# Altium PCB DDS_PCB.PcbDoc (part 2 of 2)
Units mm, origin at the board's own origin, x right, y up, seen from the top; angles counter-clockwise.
Board outline 101.55 x 88.3 mm, 8 copper layers (TOP_L1, Plane_L2, Inner_L3, Plane_L4, Plane_L5, Inner_L6, Plane_L7, Bottom Layer_L8), stack 0.681 mm thick; 434 components, 266 nets, 1385 pads, 24 vias.
Unrouted connection lines stored in the file: 977.
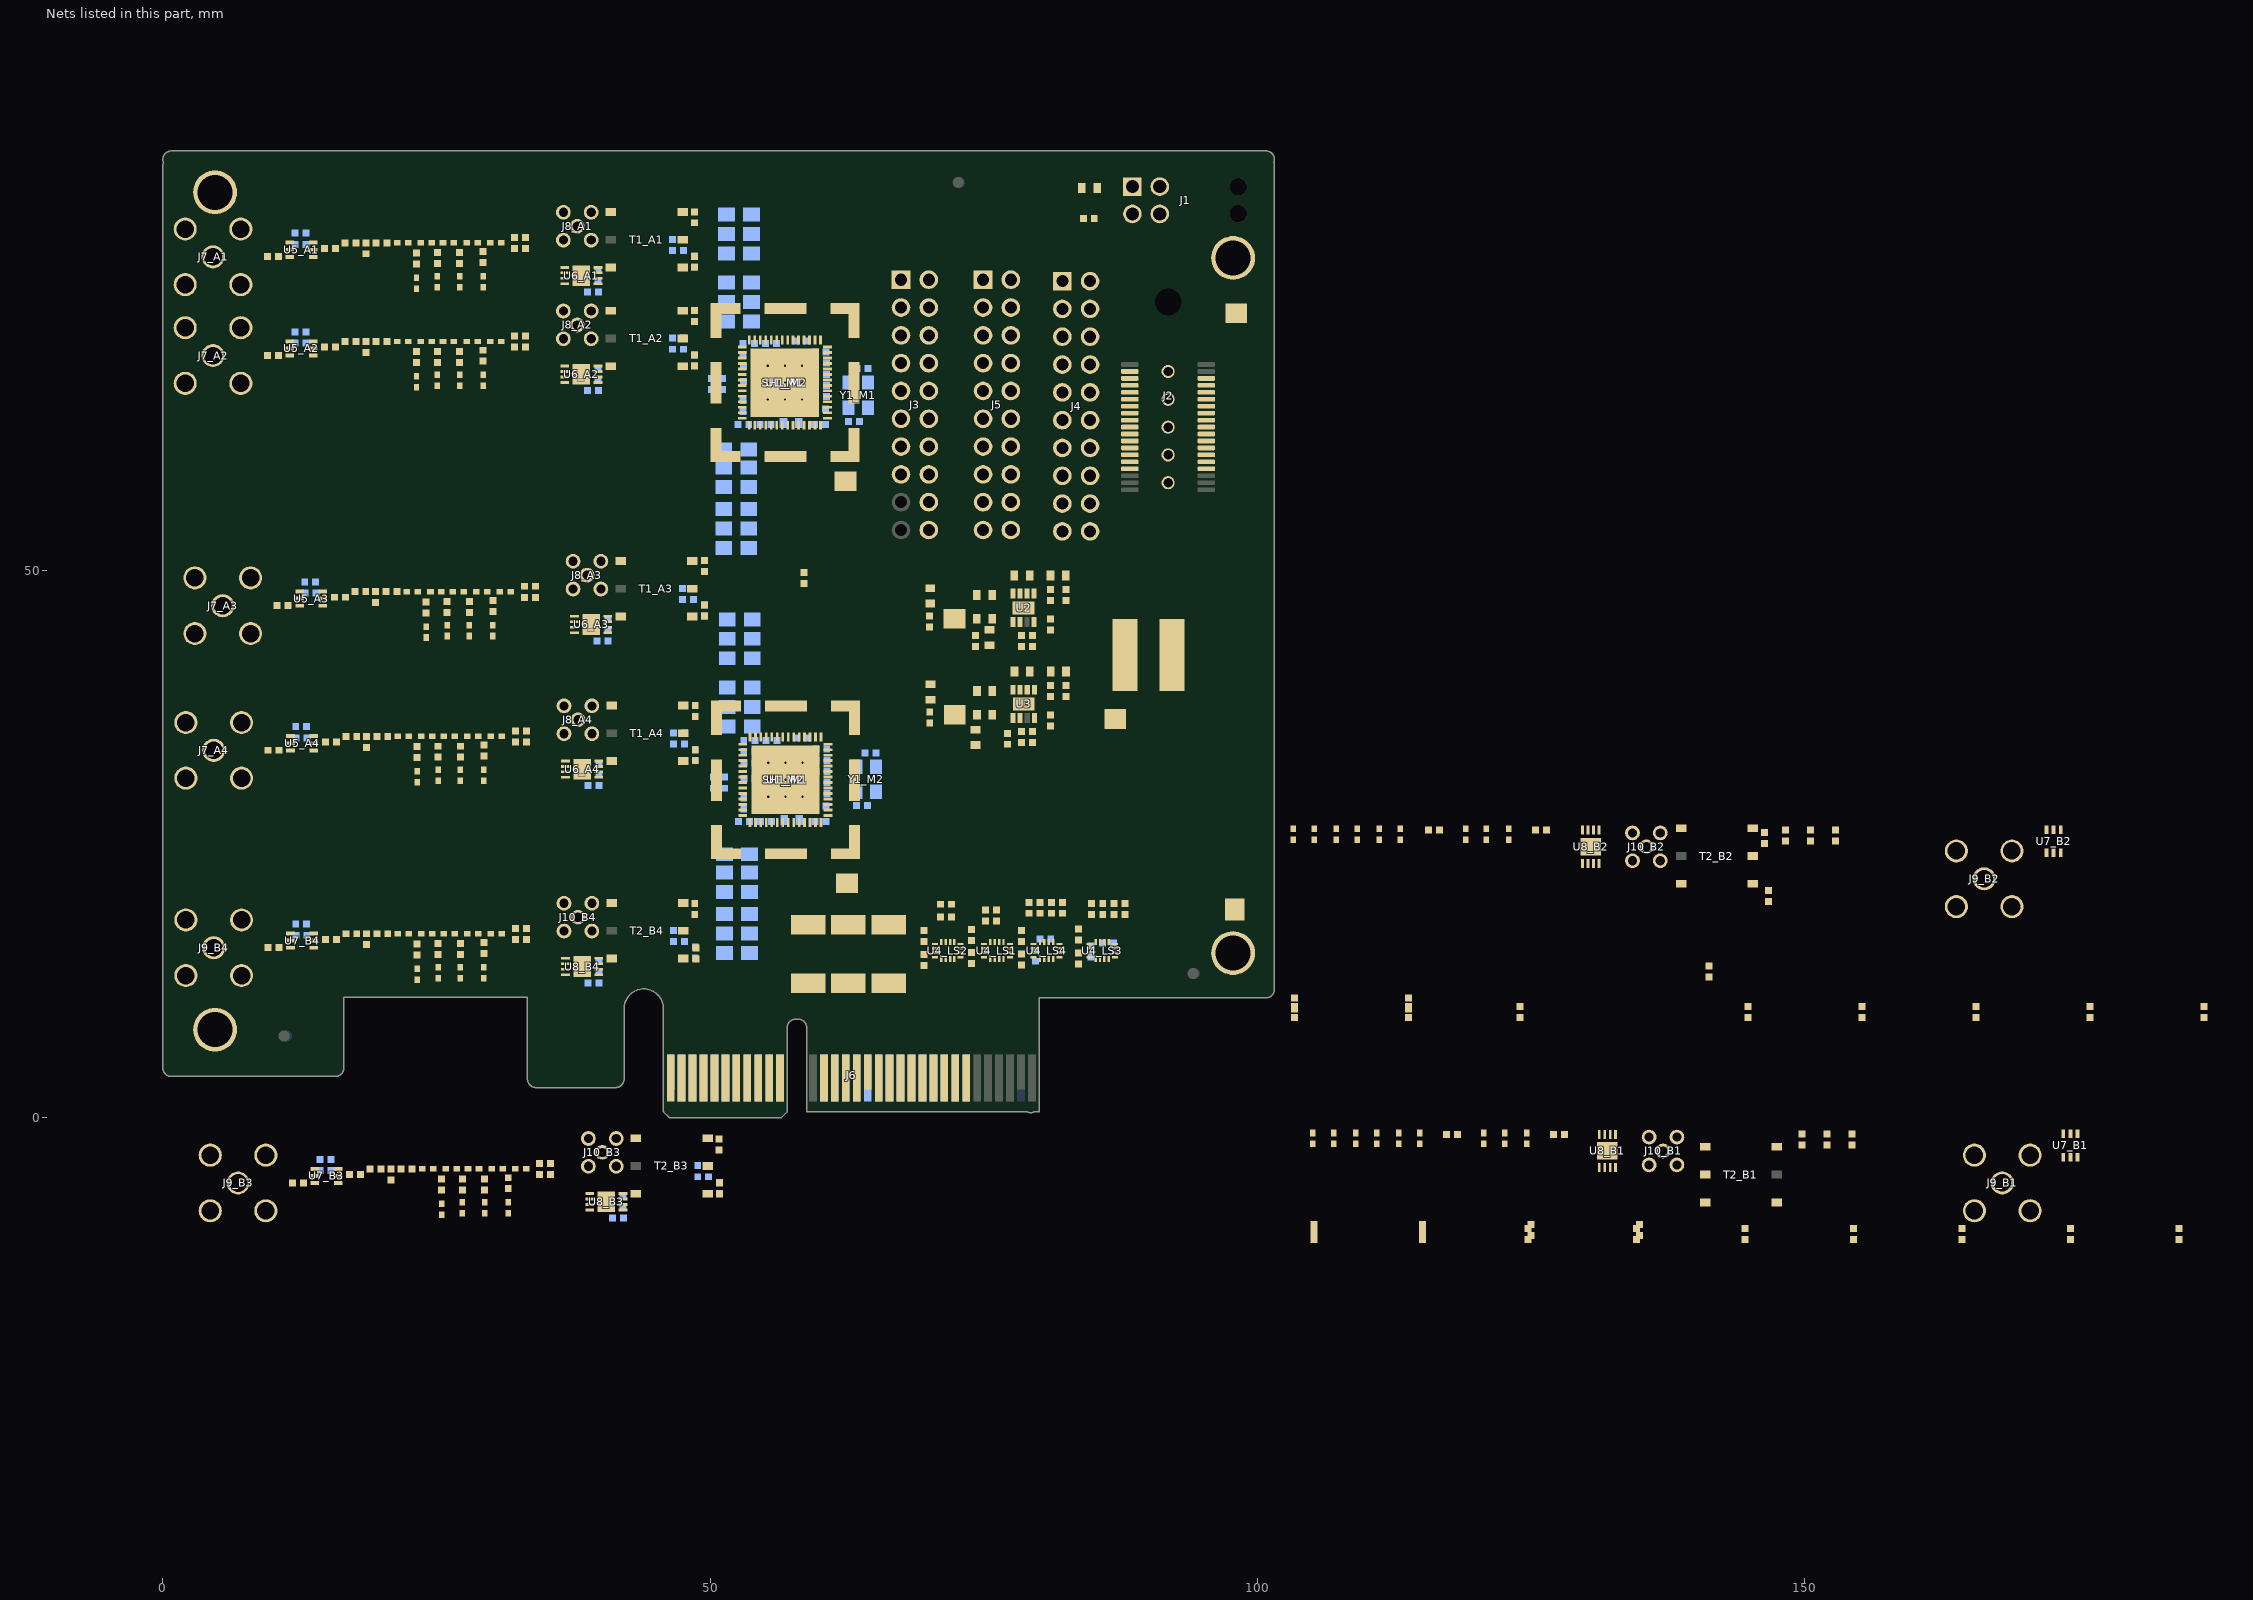
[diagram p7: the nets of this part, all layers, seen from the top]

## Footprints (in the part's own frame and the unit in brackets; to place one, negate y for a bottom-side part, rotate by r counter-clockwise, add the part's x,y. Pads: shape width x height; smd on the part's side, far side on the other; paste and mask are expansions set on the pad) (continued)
SAMTEC_MMCX-J-P-H-ST-TH1 [mm]
  round 1.348 hole 0.84: 1(0,0) S1(-1.27,1.27) S2(1.27,1.27) S3(1.27,-1.27) S4(-1.27,-1.27)
  silkscreen extent -1.75,-1.75 1.75,1.75, body extent -1.75,-1.75 1.75,1.75, height 4.35
SMD4_ECX-32_3P2X2P5_ECS [mm]
  rect 1.1x1.3 smd paste-0.55 mask+0.051: 1(-0.9,1.15) 2(-0.9,-1.15) 3(0.9,-1.15) 4(0.9,1.15)
  silkscreen extent -1.42,-0.17 1.42,0.17, body extent -1.3,-1.65 1.3,1.65, height 0.81
SMS201F [mm]
  rect 1x3.12 smd mask+0.051: 1(-6.3,-5.695) 1(6.3,-5.695)
  rect 1x3.79 smd mask+0.051: 1(-6.3,-0.03) 1(6.3,-0.03)
  rect 1x3.18 smd mask+0.051: 1(-6.3,5.665) 1(6.3,5.665)
  rect 1.75x1 smd mask+0.051: 1(-4.925,-6.755) 1(-4.925,6.755)
  rect 3.81x1 smd mask+0.051: 1(0.045,-6.755) 1(0.045,6.755)
  rect 1.64x1 smd mask+0.051: 1(4.98,-6.755) 1(4.98,6.755)
  silkscreen extent -6.35,-6.84 6.35,6.84, body extent -6.7,-7.15 6.7,7.15, height 2.64
SO8_MUN12AD_DEA [mm]
  rect 0.91x0.458 smd paste+0 mask+0.051: 1(-1.293,0.975) 2(-1.293,0.325) 3(-1.293,-0.325) 4(-1.293,-0.975) 5(1.293,-0.975) 6(1.293,-0.325) 7(1.293,0.325) 8(1.293,0.975)
  rect 1.2x2 smd paste+0 mask+0.051: 9(0,0)
  silkscreen extent -1.57,-1.68 1.57,1.68, body extent -1.45,-1.55 1.45,1.55, height 1.5
SOT_2815,115_NXP [mm]
  rect 0.782x0.355 smd paste+0 mask+0.051: 1(-1.064,0.65) 2(-1.064,0) 3(-1.064,-0.65) 4(1.064,-0.65) 5(1.064,0) 6(1.064,0.65)
  silkscreen extent -0.8,-1.23 0.8,1.23, body extent -1.1,-1.1 1.1,1.1, height 1.09
TP_2X1.8 [mm]
  rect 1.8x2 smd mask+0.051: 1(0,0)
  body extent -0.89,-0.99 0.89,0.99, height 0.03

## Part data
C1_M1 C1_M2: library part "CAP CER 6.8pF 50V NP0 0402", "CAP CER 680PF 50V NP0 0402", Capacitance=680pF, Manufacturer="TDK Corporation", Manufacturer Part Number=C1005C0G1H6R8D, Package / Case="0402 (1005 Metric)", Voltage - Rated=50V
C2_M1 C2_M2 C3_M1 C3_M2: library part "CAP CER 6.8pF 50V NP0 0402", "CAP CER 39PF 50V NP0 0402", Capacitance=39pF, Manufacturer="TDK Corporation", Manufacturer Part Number=C1005C0G1H6R8D, Package / Case="0402 (1005 Metric)", Voltage - Rated=50V
C4_M1 C4_M2 C5_M1 C5_M2 C6_M1 C6_M2 C31_A1 C31_A2 C31_A3 C31_A4 C32_A1 C32_A2 C32_A3 C32_A4 C37_A1 C37_A2 C37_A3 C37_A4 C40_A1 C40_A2 C40_A3 C40_A4 C44_B1 C44_B2 C44_B3 C44_B4 C45_B1 C45_B2 C45_B3 C45_B4 C50_B1 C50_B2 C50_B3 C50_B4 C53_B1 C53_B2 C53_B3 C53_B4: library part "CAP CER 6.8pF 50V NP0 0402", "CAP CER 1uF 25V X5R 0402", Capacitance=1uF, Manufacturer="TDK Corporation", Manufacturer Part Number=C1005C0G1H6R8D, Package / Case="0402 (1005 Metric)", Voltage - Rated=50V
C7_M1 C7_M2 C8_M1 C8_M2 C9_M1 C9_M2 C43_A1 C43_A2 C43_A3 C43_A4 C56_B1 C56_B2 C56_B3 C56_B4: library part "CAP CER 6.8pF 50V NP0 0402", "CAP CER 10uF 10V X5R 0402", Capacitance=10uF, Manufacturer="TDK Corporation", Manufacturer Part Number=C1005C0G1H6R8D, Package / Case="0402 (1005 Metric)", Voltage - Rated=50V
C10_M1 C10_M2 C11_M1 C11_M2 C12_M1 C12_M2 C29_LS1 C29_LS2 C29_LS3 C29_LS4 C30_LS1 C30_LS2 C30_LS3 C30_LS4 C38_A1 C38_A2 C38_A3 C38_A4 C39_A1 C39_A2 C39_A3 C39_A4 C41_A1 C41_A2 C41_A3 C41_A4 C42_A1 C42_A2 C42_A3 C42_A4 C51_B1 C51_B2 C51_B3 C51_B4 C52_B1 C52_B2 C52_B3 C52_B4 C54_B1 C54_B2 C54_B3 C54_B4 C55_B1 C55_B2 C55_B3 C55_B4: library part "CAP CER 6.8pF 50V NP0 0402", "CAP CER 0.1uF 50V NP0 0402", Capacitance=0.1uF, Manufacturer="TDK Corporation", Manufacturer Part Number=C1005C0G1H6R8D, Package / Case="0402 (1005 Metric)", Voltage - Rated=50V
C13 C20 C26: library part "CAP CER 10uF 10V 10% X5R 0603", "CAP CER 10UF 25V 10% X5R 0603", Capacitance=10µF, Manufacturer="TDK Corporation", Manufacturer Part Number=C1608X5R1A106K, Package / Case="0603 (1608 Metric)", Voltage - Rated=10V
C14 C15 C18 C19 C22 C24 C25: library part "CAP CER 12nF 25V 10% X7R 0402", "CAP CER 10nF 25V 10% X5R 0402", Capacitance=10nF, Manufacturer="Murata Electronics North America", Manufacturer Part Number=GRM155R71E123KA61D, Package / Case="0402 (1005 Metric)", Voltage - Rated=25V
C16 C17 C23 C27: library part "CAP CER 10uF 10V 10% X5R 0603", "CAP CER 22UF 16V 10% X5R 0603", Capacitance=22µF, Manufacturer="TDK Corporation", Manufacturer Part Number=C1608X5R1A106K, Package / Case="0603 (1608 Metric)", Voltage - Rated=10V
C21 C28: library part "CAP CER 6.8pF 50V NP0 0402", "CAP CER NA 50V NP0 0402", Manufacturer="TDK Corporation", Manufacturer Part Number=C1005C0G1H6R8D, Package / Case="0402 (1005 Metric)", Voltage - Rated=50V
C33_A1 C33_A2 C33_A3 C33_A4 C46_B1 C46_B2 C46_B3 C46_B4: library part "CAP CER 20pF 50V 5% NP0 0402", "CAP CER 16PF 50V 5% NP0 0402", Capacitance=16pF, Manufacturer="TDK Corporation", Manufacturer Part Number=C1005C0G1H200J, Package / Case="0402 (1005 Metric)", Voltage - Rated=50V
C34_A1 C34_A2 C34_A3 C34_A4 C47_B1 C47_B2 C47_B3 C47_B4: library part "CAP CER 20pF 50V 5% NP0 0402", "CAP CER 11PF 50V 5% NP0 0402", Capacitance=11pF, Manufacturer="TDK Corporation", Manufacturer Part Number=C1005C0G1H200J, Package / Case="0402 (1005 Metric)", Voltage - Rated=50V
C35_A1 C35_A2 C35_A3 C35_A4 C48_B1 C48_B2 C48_B3 C48_B4: library part "CAP CER 20pF 50V 5% NP0 0402", "CAP CER 10PF 50V 5% NP0 0402", Capacitance=10pF, Manufacturer="TDK Corporation", Manufacturer Part Number=C1005C0G1H200J, Package / Case="0402 (1005 Metric)", Voltage - Rated=50V
C36_A1 C36_A2 C36_A3 C36_A4 C49_B1 C49_B2 C49_B3 C49_B4: library part "CAP CER 20pF 50V 5% NP0 0402", "CAP CER 13PF 50V 5% NP0 0402", Capacitance=13pF, Manufacturer="TDK Corporation", Manufacturer Part Number=C1005C0G1H200J, Package / Case="0402 (1005 Metric)", Voltage - Rated=50V
F1 F2 F3: library part 1812L150/24MR, "FUSE PTC 24V 1.5A POLYFUSE 1812", Current - Hold (Ih) (Max)=1.5A, Manufacturer="Littelfuse Inc", Package / Case="1812 (4532 Metric), Concave"
FB1_M1 FB1_M2 FB2 FB3 FB4 FB5: library part BK1608HS600-T, "FERRITE BEAD 220_OHM@100MHz 0603 2A 50mohm_DC", Manufacturer="Taiyo Yuden", Package / Case="0603 (1608 Metric)"
H1 H2 H3 H4: "hole 3mm"
J1: "No Description Available", Mfr_Name="Molex Connector Corporation"
J2: "CONN MICTOR 38POS .025 VERT SMD", Manufacturer="TE Connectivity"
J3 J4 J5: "CONN HEADER 20 TH", Manufacturer="Molex Connector Corporation"
J6: "64 Position Female Connector PCI Expressâ„¢ Gold 0.039 _1.00mm_ Black", Package=None
J7_A1 J7_A2 J7_A3 J7_A4 J9_B1 J9_B2 J9_B3 J9_B4: "No Description Available", Mfr_Name="Samtec Inc"
J8_A1 J8_A2 J8_A3 J8_A4 J10_B1 J10_B2 J10_B3 J10_B4: "MMCX STRAIGHT, THROUGH HOLE JACK- 50 OHM", Package=None
LD1 LD2: "LED 1.6X0.8MM 568NM GRN CLR SMD", Manufacturer="Kingbright Corp", Package / Case="0603 (1608 Metric)"
Lp1: "INDUCTOR 10UH 1.9A 20% SMD", Manufacturer="Taiyo Yuden", Package / Case="Non Standard"
R1_M1 R1_M2: library part "RES 3.09K OHM 1/16W 1% 0402", "RES 6.8K OHM 1/16W 1% 0402", Manufacturer="Stackpole Electronics Inc", Manufacturer Part Number=RMCF0402FT3K09, Package / Case="0402 (1005 Metric)", Power (Watts)="0.063W, 1/16W", Supplier Device Package=0402
R2_M1 R2_M2 R7_M1 R7_M2 R8_M1 R8_M2 R9_M1 R9_M2 R10_M1 R10_M2 R33 R41_A1 R41_A2 R41_A3 R41_A4 R42_A1 R42_A2 R42_A3 R42_A4 R48_B1 R48_B2 R48_B3 R48_B4 R49_B1 R49_B2 R49_B3 R49_B4: library part "RES 100 OHM 1/10W 1% 0402 SMD", "RES 0 OHM 1/10W 1% 0402 SMD", Manufacturer="Panasonic Electronic Components", Manufacturer Part Number=ERJ-2RKF1000X, Package / Case="0402 (1005 Metric)", Supplier Device Package=0402
R3_M1 R3_M2 R4_M1 R4_M2 R5_M1 R5_M2 R6_M1 R6_M2 R11_M1 R11_M2 R12_M1 R12_M2 R13_M1 R13_M2 R14_M1 R14_M2: library part "RES 3.09K OHM 1/16W 1% 0402", "RES 10K OHM 1/16W 1% 0402", Manufacturer="Stackpole Electronics Inc", Manufacturer Part Number=RMCF0402FT3K09, Package / Case="0402 (1005 Metric)", Power (Watts)="0.063W, 1/16W", Supplier Device Package=0402
R15_M1 R15_M2 R16_M1 R16_M2 R17_M1 R17_M2 R18_M1 R18_M2 R19_M1 R19_M2 R20_M1 R20_M2 R21_M1 R21_M2 R22_M1 R22_M2 R23_M1 R23_M2 R24_M1 R24_M2 R25_M1 R25_M2 R26_M1 R26_M2: library part "RES 200 OHM 1/8W 1% 0805 SMD", "RES 0 OHM 1/8W 1% 0805 SMD", Manufacturer="Stackpole Electronics Inc", Manufacturer Part Number=RMCF0805FT200R, Package / Case="0805 (2012 Metric)", Power (Watts)="0.125W, 1/8W", Supplier Device Package=0805
R27 R30: library part "RES 15.4K OHM 1/10W 1% 0402 SMD", "RES 124K OHM 1/10W 1% 0402 SMD", Manufacturer="Panasonic Electronic Components", Manufacturer Part Number=ERJ-2RKF1542X, Package / Case="0402 (1005 Metric)", Power (Watts)="0.1W, 1/10W", Supplier Device Package=0402
R28 R31: library part "RES 3.09K OHM 1/16W 1% 0402", "RES 1K OHM 1/16W 1% 0402", Manufacturer="Stackpole Electronics Inc", Manufacturer Part Number=RMCF0402FT3K09, Package / Case="0402 (1005 Metric)", Power (Watts)="0.063W, 1/16W", Supplier Device Package=0402
R29: library part "RES 15.4K OHM 1/10W 1% 0402 SMD", "RES 39.2K OHM 1/10W 1% 0402 SMD", Manufacturer="Panasonic Electronic Components", Manufacturer Part Number=ERJ-2RKF1542X, Package / Case="0402 (1005 Metric)", Power (Watts)="0.1W, 1/10W", Supplier Device Package=0402
R32 R34_LS1 R34_LS2 R34_LS3 R34_LS4: library part "RES 3.09K OHM 1/16W 1% 0402", "RES 100K OHM 1/16W 1% 0402", Manufacturer="Stackpole Electronics Inc", Manufacturer Part Number=RMCF0402FT3K09, Package / Case="0402 (1005 Metric)", Power (Watts)="0.063W, 1/16W", Supplier Device Package=0402
R35_LS1 R35_LS2 R35_LS3 R35_LS4: library part "RES 3.09K OHM 1/16W 1% 0402", "RES 3.09K OHM 1/16W 1% 0402", Manufacturer="Stackpole Electronics Inc", Manufacturer Part Number=RMCF0402FT3K09, Package / Case="0402 (1005 Metric)", Power (Watts)="0.063W, 1/16W", Supplier Device Package=0402
R36_A1 R36_A2 R36_A3 R36_A4 R37_A1 R37_A2 R37_A3 R37_A4 R43_B1 R43_B2 R43_B3 R43_B4 R44_B1 R44_B2 R44_B3 R44_B4: library part "RES 100 OHM 1/10W 1% 0402 SMD", "RES 34.8 OHM 1/10W 1% 0402 SMD", Manufacturer="Panasonic Electronic Components", Manufacturer Part Number=ERJ-2RKF1000X, Package / Case="0402 (1005 Metric)", Supplier Device Package=0402
R38_A1 R38_A2 R38_A3 R38_A4 R45_B1 R45_B2 R45_B3 R45_B4: library part "RES 100 OHM 1/10W 1% 0402 SMD", "RES 18.2 OHM 1/10W 1% 0402 SMD", Manufacturer="Panasonic Electronic Components", Manufacturer Part Number=ERJ-2RKF1000X, Package / Case="0402 (1005 Metric)", Supplier Device Package=0402
R39_A1 R39_A2 R39_A3 R39_A4 R40_A1 R40_A2 R40_A3 R40_A4 R46_B1 R46_B2 R46_B3 R46_B4 R47_B1 R47_B2 R47_B3 R47_B4: library part "RES 100 OHM 1/10W 1% 0402 SMD", "RES 49.9 OHM 1/10W 1% 0402 SMD", Manufacturer="Panasonic Electronic Components", Manufacturer Part Number=ERJ-2RKF1000X, Package / Case="0402 (1005 Metric)", Supplier Device Package=0402
SH1_M1 SH1_M2: "RF SHIELD 0.5\" X 0.538\" SMD", Manufacturer="Leader Tech Inc.", Manufacturer_Part_Number=SMS-201F
T1_A1 T1_A2 T1_A3 T1_A4 T2_B1 T2_B2 T2_B3 T2_B4: "No Description Available", Mfr_Name="Mini Circuits"
TP1 TP2 TP3 TP4 TP5 TP6: library part "TP mini_2", "TP PC MINIATURE SMT", Manufacturer="Keystone Electronics", Manufacturer Part Number=5015
TP7: library part "TP mini_1", "TP PC MINIATURE SMT", Manufacturer="Keystone Electronics", Manufacturer Part Number=5015
U1_M1 U1_M2 U6_A1 U6_A2 U6_A3 U6_A4 U8_B1 U8_B2 U8_B3 U8_B4: "No Description Available", Mfr_Name="Analog Devices Inc"
U2 U3: "No Description Available", Mfr_Name=Delta
U5_A1 U5_A2 U5_A3 U5_A4 U7_B1 U7_B2 U7_B3 U7_B4: "No Description Available", Mfr_Name=NXP
Y1_M1 Y1_M2: "No Description Available", Mfr_Name="ECS International"

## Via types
v1: diameter 0.406, hole 0.203, TOP_L1 to Bottom Layer_L8, tented both sides, 18 vias
v2: diameter 0.65, hole 0.3, TOP_L1 to Bottom Layer_L8, tented both sides, 6 vias

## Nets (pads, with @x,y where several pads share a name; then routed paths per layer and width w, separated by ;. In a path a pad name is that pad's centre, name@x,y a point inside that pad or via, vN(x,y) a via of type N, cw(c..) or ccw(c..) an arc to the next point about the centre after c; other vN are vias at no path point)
1.8V: C23.2 C27.2 FB5.1 R30.2 U3.4 U3.5
1_8V: F2.1 J6.B5 J6.B6 J6.B7 J6.B8
3.3V: C16.2 C17.2 FB3.1 R27.2 U2.4 U2.5
3_3V: F1.1 J6.B1 J6.B2 J6.B3 J6.B4
12_V: F3.2 J6.A1 J6.A2 J6.A3 J6.A4
12v_1: C19.2 C20.2 FB2.2 U2.1 U2.2
12v_2: C25.2 C26.2 FB4.2 U3.1 U3.2
12v_in: C13.2 C14.2 J1.1 J1.2 Lp1.1
AVDD0_M1: C41_A1.2 C42_A1.2 C43_A1.2 C54_B1.2 C55_B1.2 C56_B1.2 R18_M1.2 R22_M1.2 R26_M1.2 R39_A1.2 R40_A1.1 R46_B1.2 R47_B1.1 T1_A1.2 T2_B1.2
AVDD0_M2: C41_A3.2 C42_A3.2 C43_A3.2 C54_B3.2 C55_B3.2 C56_B3.2 R18_M2.2 R22_M2.2 R26_M2.2 R39_A3.2 R40_A3.1 R46_B3.2 R47_B3.1 T1_A3.2 T2_B3.2
AVDD1_M1: C41_A2.2 C42_A2.2 C43_A2.2 C54_B2.2 C55_B2.2 C56_B2.2 R17_M1.2 R18_M1.1 R21_M1.2 R22_M1.1 R25_M1.2 R26_M1.1 R39_A2.2 R40_A2.1 R46_B2.2 R47_B2.1 T1_A2.2 T2_B2.2
AVDD1_M2: C41_A4.2 C42_A4.2 C43_A4.2 C54_B4.2 C55_B4.2 C56_B4.2 R17_M2.2 R18_M2.1 R21_M2.2 R22_M2.1 R25_M2.2 R26_M2.1 R39_A4.2 R40_A4.1 R46_B4.2 R47_B4.1 T1_A4.2 T2_B4.2
AVDD2_M1: R16_M1.2 R17_M1.1 R20_M1.2 R21_M1.1 R24_M1.2 R25_M1.1
AVDD2_M2: R16_M2.2 R17_M2.1 R20_M2.2 R21_M2.1 R24_M2.2 R25_M2.1
AVDD3_M1: R15_M1.2 R16_M1.1 R19_M1.2 R20_M1.1 R23_M1.2 R24_M1.1
AVDD3_M2: R15_M2.2 R16_M2.1 R19_M2.2 R20_M2.1 R23_M2.2 R24_M2.1
CH_B1_N: R47_B1.2 T2_B1.1
CH_B1_P: R46_B1.1 T2_B1.3
CH_B2_N: R47_B2.2 T2_B2.1
CH_B2_P: R46_B2.1 T2_B2.3
CH_B3_N: R47_B3.2 T2_B3.1
CH_B3_P: R46_B3.1 T2_B3.3
CH_B4_N: R47_B4.2 T2_B4.1
CH_B4_P: R46_B4.1 T2_B4.3
CH_N0_M1: R40_A1.2 T1_A1.3 U1_M1.29
CH_N0_M2: R40_A3.2 T1_A3.3 U1_M2.29
CH_N1_M1: R40_A2.2 T1_A2.3 U1_M1.35
CH_N1_M2: R40_A4.2 T1_A4.3 U1_M2.35
CH_N2_M1: U1_M1.9
CH_N2_M2: U1_M2.9
CH_N3_M1: U1_M1.14
CH_N3_M2: U1_M2.14
CH_P0_M1: R39_A1.1 T1_A1.1 U1_M1.30
CH_P0_M2: R39_A3.1 T1_A3.1 U1_M2.30
CH_P1_M1: R39_A2.1 T1_A2.1 U1_M1.36
CH_P1_M2: R39_A4.1 T1_A4.1 U1_M2.36
CH_P2_M1: U1_M1.8
CH_P2_M2: U1_M2.8
CH_P3_M1: U1_M1.13
CH_P3_M2: U1_M2.13
CLK_sel_M1: R8_M1.1 R10_M1.2 U1_M1.24
CLK_sel_M2: R8_M2.1 R10_M2.2 U1_M2.24
contr0_M1: J2.26 J3.1 J6.B13 U6_A1.2 U8_B1.2
contr0_M2: J2.25 J3.9 J6.A13 U6_A3.2 U8_B3.2
contr1_M1: J2.28 J3.3 J6.B14 U6_A2.2 U8_B2.2
contr1_M2: J2.27 J3.11 J6.A14 U6_A4.2 U8_B4.2
contr2_M1: J2.30 J3.5 J6.B15
contr2_M2: J2.29 J3.13 J6.A15
contr3_M1: J2.32 J3.7 J6.B16
contr3_M2: J2.31 J3.15 J6.A16
CSn: U1_M1.47 U4_LS2.12
CSn_2: U1_M2.47 U4_LS1.12
CSn_2_L: J2.7 J5.3 J6.A18 U4_LS1.1
CSn_L: J2.8 J4.3 J6.B18 U4_LS2.1
DAC_O_A1: T1_A1.6 U6_A1.4
DAC_O_A2: T1_A2.6 U6_A2.4
DAC_O_A3: T1_A3.6 U6_A3.4
DAC_O_A4: T1_A4.6 U6_A4.4
DAC_O_B1: T2_B1.4 U8_B1.4
DAC_O_B2: T2_B2.4 U8_B2.4
DAC_O_B3: T2_B3.4 U8_B3.4
DAC_O_B4: T2_B4.4 U8_B4.4
DIR_LS1: J2.21 J5.17 J6.A25 R34_LS1.1 R34_LS4.1 R35_LS1.2 R35_LS4.2 U4_LS1.5 U4_LS1.6 U4_LS1.15 U4_LS1.16 U4_LS4.5 U4_LS4.6 U4_LS4.15 U4_LS4.16
DIR_LS2: J2.22 J4.17 J6.B25 R34_LS2.1 R34_LS3.1 R35_LS2.2 R35_LS3.2 U4_LS2.5 U4_LS2.6 U4_LS2.15 U4_LS2.16 U4_LS3.5 U4_LS3.6 U4_LS3.15 U4_LS3.16
FB_1.8: R30.1 R32.2 U3.6
FB_3.3: R27.1 R29.2 U2.6
GND: C2_M1.2 C2_M2.2 C3_M1.1 C3_M2.1 C4_M1.1 C4_M2.1 C5_M1.1 C5_M2.1 C6_M1.1 C6_M2.1 C7_M1.1 C7_M2.1 C8_M1.1 C8_M2.1 C9_M1.1 C9_M2.1 C10_M1.1 C10_M2.1 C11_M1.1 C11_M2.1 C12_M1.1 C12_M2.1 C13.1 C14.1 C15.1 C16.1 C17.1 C18.1 C19.1 C20.1 C21.1 C22.1 C23.1 C24.1 C25.1 C26.1 C27.1 C28.1 C29_LS1.1 C29_LS2.1 C29_LS3.1 C29_LS4.1 C30_LS1.1 C30_LS2.1 C30_LS3.1 C30_LS4.1 C37_A1.1 C37_A2.1 C37_A3.1 C37_A4.1 C38_A1.1 C38_A2.1 C38_A3.1 C38_A4.1 C39_A1.1 C39_A2.1 C39_A3.1 C39_A4.1 C40_A1.1 C40_A2.1 C40_A3.1 C40_A4.1 C41_A1.1 C41_A2.1 C41_A3.1 C41_A4.1 C42_A1.1 C42_A2.1 C42_A3.1 C42_A4.1 C43_A1.1 C43_A2.1 C43_A3.1 C43_A4.1 C50_B1.1 C50_B2.1 C50_B3.1 C50_B4.1 C51_B1.1 C51_B2.1 C51_B3.1 C51_B4.1 C52_B1.1 C52_B2.1 C52_B3.1 C52_B4.1 C53_B1.1 C53_B2.1 C53_B3.1 C53_B4.1 C54_B1.1 C54_B2.1 C54_B3.1 C54_B4.1 C55_B1.1 C55_B2.1 C55_B3.1 C55_B4.1 C56_B1.1 C56_B2.1 C56_B3.1 C56_B4.1 H1.1 H2.1 H3.1 H4.1 J1.3 J1.4 J2.3 J2.39 J2.40 J2.41 J2.42 J2.43 J3.2 J3.4 J3.6 J3.8 J3.10 J3.12 J3.14 J3.16 J3.18 J3.20 J4.2 J4.4 J4.6 J4.8 J4.10 J4.12 J4.14 J4.16 J4.18 J4.20 J5.2 J5.4 J5.6 J5.8 J5.10 J5.12 J5.14 J5.16 J5.18 J5.20 J6.A5 J6.A6 J6.A7 J6.A8 J6.A9 J6.A10 J6.A11 J6.B9 J6.B10 J6.B11 J7_A1.2 J7_A1.3 J7_A1.4 J7_A1.5 J7_A2.2 J7_A2.3 J7_A2.4 J7_A2.5 J7_A3.2 J7_A3.3 J7_A3.4 J7_A3.5 J7_A4.2 J7_A4.3 J7_A4.4 J7_A4.5 J8_A1.S1 J8_A1.S2 J8_A1.S3 J8_A1.S4 J8_A2.S1 J8_A2.S2 J8_A2.S3 J8_A2.S4 J8_A3.S1 J8_A3.S2 J8_A3.S3 J8_A3.S4 J8_A4.S1 J8_A4.S2 J8_A4.S3 J8_A4.S4 J9_B1.2 J9_B1.3 J9_B1.4 J9_B1.5 J9_B2.2 J9_B2.3 J9_B2.4 J9_B2.5 J9_B3.2 J9_B3.3 J9_B3.4 J9_B3.5 J9_B4.2 J9_B4.3 J9_B4.4 J9_B4.5 J10_B1.S1 J10_B1.S2 J10_B1.S3 J10_B1.S4 J10_B2.S1 J10_B2.S2 J10_B2.S3 J10_B2.S4 J10_B3.S1 J10_B3.S2 J10_B3.S3 J10_B3.S4 J10_B4.S1 J10_B4.S2 J10_B4.S3 J10_B4.S4 L6_A1.2 L6_A2.2 L6_A3.2 L6_A4.2 L7_A1.2 L7_A2.2 L7_A3.2 L7_A4.2 L8_A1.2 L8_A2.2 L8_A3.2 L8_A4.2 L9_A1.2 L9_A2.2 L9_A3.2 L9_A4.2 L15_B1.2 L15_B2.2 L15_B3.2 L15_B4.2 L16_B1.2 L16_B2.2 L16_B3.2 L16_B4.2 L17_B1.2 L17_B2.2 L17_B3.2 L17_B4.2 L18_B1.2 L18_B2.2 L18_B3.2 L18_B4.2 LD1.2 LD2.2 R1_M1.1 R1_M2.1 R3_M1.1 R3_M2.1 R4_M1.1 R4_M2.1 R5_M1.1 R5_M2.1 R6_M1.1 R6_M2.1 R9_M1.1 R9_M2.1 R10_M1.1 R10_M2.1 R11_M1.1 R11_M2.1 R12_M1.1 R12_M2.1 R13_M1.1 R13_M2.1 R14_M1.1 R14_M2.1 R29.1 R32.1 R35_LS1.1 R35_LS2.1 R35_LS3.1 R35_LS4.1 R38_A1.2 R38_A2.2 R38_A3.2 R38_A4.2 R45_B1.2 R45_B2.2 R45_B3.2 R45_B4.2 SH1_M1.1 SH1_M2.1 T1_A1.4 T1_A2.4 T1_A3.4 T1_A4.4 T2_B1.6 T2_B2.6 T2_B3.6 T2_B4.6 TP6.1 TP7.1 U1_M1.6 U1_M1.10 U1_M1.12 U1_M1.16 U1_M1.18 U1_M1.20 U1_M1.25 U1_M1.28 U1_M1.32 U1_M1.34 U1_M1.38 U1_M1.44 U1_M1.56 U1_M1.57 U1_M2.6 U1_M2.10 U1_M2.12 U1_M2.16 U1_M2.18 U1_M2.20 U1_M2.25 U1_M2.28 U1_M2.32 U1_M2.34 U1_M2.38 U1_M2.44 U1_M2.56 U1_M2.57 U2.3 U2.9 U3.3 U3.9 U4_LS1.7 U4_LS1.8 U4_LS2.7 U4_LS2.8 U4_LS3.7 U4_LS3.8 U4_LS4.7 U4_LS4.8 U5_A1.2 U5_A1.4 U5_A1.5 U5_A2.2 U5_A2.4 U5_A2.5 U5_A3.2 U5_A3.4 U5_A3.5 U5_A4.2 U5_A4.4 U5_A4.5 U6_A1.3 U6_A1.5 U6_A1.6 U6_A1.7 U6_A1.9 U6_A2.3 U6_A2.5 U6_A2.6 U6_A2.7 U6_A2.9 U6_A3.3 U6_A3.5 U6_A3.6 U6_A3.7 U6_A3.9 U6_A4.3 U6_A4.5 U6_A4.6 U6_A4.7 U6_A4.9 U7_B1.2 U7_B1.4 U7_B1.5 U7_B2.2 U7_B2.4 U7_B2.5 U7_B3.2 U7_B3.4 U7_B3.5 U7_B4.2 U7_B4.4 U7_B4.5 U8_B1.3 U8_B1.5 U8_B1.6 U8_B1.7 U8_B1.9 U8_B2.3 U8_B2.5 U8_B2.6 U8_B2.7 U8_B2.9 U8_B3.3 U8_B3.5 U8_B3.6 U8_B3.7 U8_B3.9 U8_B4.3 U8_B4.5 U8_B4.6 U8_B4.7 U8_B4.9 Y1_M1.2 Y1_M1.4 Y1_M2.2 Y1_M2.4
  other v1: 55.293,29.289 56.868,29.289 58.417,29.289 55.293,30.838 56.868,30.838 58.417,30.838 55.293,32.388 56.868,32.388 58.417,32.388 55.241,65.571 56.816,65.571 58.365,65.571 55.241,67.12 56.816,67.12 58.365,67.12 55.241,68.669 56.816,68.669 58.365,68.669
IO_UPDATE: U1_M1.46 U4_LS2.10
IO_UPDATE_2: U1_M2.46 U4_LS1.10
IO_UPDATE_2_L: J2.9 J5.1 J6.A19 U4_LS1.3
IO_UPDATE_L: J2.10 J4.1 J6.B19 U4_LS2.3
MASTER_RESET: U1_M1.3 U4_LS2.9
MASTER_RESET_2: U1_M2.3 U4_LS1.9
MASTER_RESET_2_L: J2.11 J5.7 J6.A20 U4_LS1.4
MASTER_RESET_L: J2.12 J4.7 J6.B20 U4_LS2.4
NetC1_M1_2: C1_M1.2 R2_M1.2
NetC1_M2_2: C1_M2.2 R2_M2.2
NetC21_2: C21.2 U2.8
NetC28_2: C28.2 U3.8
NetC44_B1_1: C44_B1.1 J9_B1.1
NetC44_B2_1: C44_B2.1 J9_B2.1
NetC44_B3_1: C44_B3.1 J9_B3.1
NetC44_B4_1: C44_B4.1 J9_B4.1
NetC46_B1_1: C46_B1.1 L10_B1.1 L11_B1.2
NetC46_B1_2: C46_B1.2 L15_B1.1
NetC46_B2_1: C46_B2.1 L10_B2.1 L11_B2.2
NetC46_B2_2: C46_B2.2 L15_B2.1
NetC46_B3_1: C46_B3.1 L10_B3.1 L11_B3.2
NetC46_B3_2: C46_B3.2 L15_B3.1
NetC46_B4_1: C46_B4.1 L10_B4.1 L11_B4.2
NetC46_B4_2: C46_B4.2 L15_B4.1
NetC47_B1_1: C47_B1.1 L10_B1.2 L12_B1.1
NetC47_B1_2: C47_B1.2 L16_B1.1
NetC47_B2_1: C47_B2.1 L10_B2.2 L12_B2.1
NetC47_B2_2: C47_B2.2 L16_B2.1
NetC47_B3_1: C47_B3.1 L10_B3.2 L12_B3.1
NetC47_B3_2: C47_B3.2 L16_B3.1
NetC47_B4_1: C47_B4.1 L10_B4.2 L12_B4.1
NetC47_B4_2: C47_B4.2 L16_B4.1
NetC48_B1_1: C48_B1.1 L12_B1.2 L13_B1.1
NetC48_B1_2: C48_B1.2 L17_B1.1
NetC48_B2_1: C48_B2.1 L12_B2.2 L13_B2.1
NetC48_B2_2: C48_B2.2 L17_B2.1
NetC48_B3_1: C48_B3.1 L12_B3.2 L13_B3.1
NetC48_B3_2: C48_B3.2 L17_B3.1
NetC48_B4_1: C48_B4.1 L12_B4.2 L13_B4.1
NetC48_B4_2: C48_B4.2 L17_B4.1
NetC49_B1_1: C49_B1.1 L13_B1.2 L14_B1.1
NetC49_B1_2: C49_B1.2 L18_B1.1
NetC49_B2_1: C49_B2.1 L13_B2.2 L14_B2.1
NetC49_B2_2: C49_B2.2 L18_B2.1
NetC49_B3_1: C49_B3.1 L13_B3.2 L14_B3.1
NetC49_B3_2: C49_B3.2 L18_B3.1
NetC49_B4_1: C49_B4.1 L13_B4.2 L14_B4.1
NetC49_B4_2: C49_B4.2 L18_B4.1
NetJ8_A1_1: J8_A1.1 R41_A1.1
NetJ8_A2_1: J8_A2.1 R41_A2.1
NetJ8_A3_1: J8_A3.1 R41_A3.1
NetJ8_A4_1: J8_A4.1 R41_A4.1
NetJ10_B1_1: J10_B1.1 R48_B1.1
NetJ10_B2_1: J10_B2.1 R48_B2.1
NetJ10_B3_1: J10_B3.1 R48_B3.1
NetJ10_B4_1: J10_B4.1 R48_B4.1
NetL11_B1_1: L11_B1.1 R49_B1.2
NetL11_B2_1: L11_B2.1 R49_B2.2
NetL11_B3_1: L11_B3.1 R49_B3.2
NetL11_B4_1: L11_B4.1 R49_B4.2
NetLD1_1: LD1.1 R28.1
NetLD2_1: LD2.1 R31.1
NetR1_M1_2: R1_M1.2 U1_M1.17
NetR1_M2_2: R1_M2.2 U1_M2.17
NetR2_M1_1: R2_M1.1 U1_M1.27
NetR2_M2_1: R2_M2.1 U1_M2.27
NetR43_B1_1: R43_B1.1 R44_B1.2 R45_B1.1
NetR43_B2_1: R43_B2.1 R44_B2.2 R45_B2.1
NetR43_B3_1: R43_B3.1 R44_B3.2 R45_B3.1
NetR43_B4_1: R43_B4.1 R44_B4.2 R45_B4.1
OUT_A1: L5_A1.2 R37_A1.1
OUT_A2: L5_A2.2 R37_A2.1
OUT_A3: L5_A3.2 R37_A3.1
OUT_A4: L5_A4.2 R37_A4.1
OUT_B1: L14_B1.2 R44_B1.1
OUT_B2: L14_B2.2 R44_B2.1
OUT_B3: L14_B3.2 R44_B3.1
OUT_B4: L14_B4.2 R44_B4.1
P0_M1: R11_M1.2 U1_M1.40
P0_M2: R11_M2.2 U1_M2.40
P1.8V_ana_M1: C1_M1.1 C6_M1.2 C9_M1.2 C12_M1.2 FB1_M1.2 R8_M1.2 R15_M1.1 R19_M1.1 R23_M1.1 U1_M1.5 U1_M1.7 U1_M1.11 U1_M1.15 U1_M1.19 U1_M1.21 U1_M1.26 U1_M1.31 U1_M1.33 U1_M1.37 U1_M1.39
P1.8V_ana_M2: C1_M2.1 C6_M2.2 C9_M2.2 C12_M2.2 FB1_M2.2 R8_M2.2 R15_M2.1 R19_M2.1 R23_M2.1 U1_M2.5 U1_M2.7 U1_M2.11 U1_M2.15 U1_M2.19 U1_M2.21 U1_M2.26 U1_M2.31 U1_M2.33 U1_M2.37 U1_M2.39
P1_M1: R12_M1.2 U1_M1.41
P1_M2: R12_M2.2 U1_M2.41
P2_M1: R13_M1.2 U1_M1.42
P2_M2: R13_M2.2 U1_M2.42
P3_M1: R14_M1.2 U1_M1.43
P3_M2: R14_M2.2 U1_M2.43
P12V: C15.2 C22.2 F3.1 FB2.1 FB4.1 Lp1.2 TP1.1
PWR_DWN_CTR_M1: R7_M1.1 R9_M1.2 U1_M1.4
PWR_DWN_CTR_M2: R7_M2.1 R9_M2.2 U1_M2.4
REF_CLK_M1_N: C3_M1.2 U1_M1.22 Y1_M1.1
REF_CLK_M1_P: C2_M1.1 U1_M1.23 Y1_M1.3
REF_CLK_M2_N: C3_M2.2 U1_M2.22 Y1_M2.1
REF_CLK_M2_P: C2_M2.1 U1_M2.23 Y1_M2.3
RF_1_A1: L2_A1.1 R42_A1.2
RF_1_A2: L2_A2.1 R42_A2.2
RF_1_A3: L2_A3.1 R42_A3.2
RF_1_A4: L2_A4.1 R42_A4.2
RF_2_A1: C33_A1.1 L1_A1.1 L2_A1.2
RF_2_A2: C33_A2.1 L1_A2.1 L2_A2.2
RF_2_A3: C33_A3.1 L1_A3.1 L2_A3.2
RF_2_A4: C33_A4.1 L1_A4.1 L2_A4.2
RF_3_A1: C34_A1.1 L1_A1.2 L3_A1.1
RF_3_A2: C34_A2.1 L1_A2.2 L3_A2.1
RF_3_A3: C34_A3.1 L1_A3.2 L3_A3.1
RF_3_A4: C34_A4.1 L1_A4.2 L3_A4.1
RF_4_A1: C35_A1.1 L3_A1.2 L4_A1.1
RF_4_A2: C35_A2.1 L3_A2.2 L4_A2.1
RF_4_A3: C35_A3.1 L3_A3.2 L4_A3.1
RF_4_A4: C35_A4.1 L3_A4.2 L4_A4.1
RF_5_A1: C36_A1.1 L4_A1.2 L5_A1.1
RF_5_A2: C36_A2.1 L4_A2.2 L5_A2.1
RF_5_A3: C36_A3.1 L4_A3.2 L5_A3.1
RF_5_A4: C36_A4.1 L4_A4.2 L5_A4.1
RF_6_A1: C33_A1.2 L9_A1.1
RF_6_A2: C33_A2.2 L9_A2.1
RF_6_A3: C33_A3.2 L9_A3.1
RF_6_A4: C33_A4.2 L9_A4.1
RF_7_A1: C34_A1.2 L6_A1.1
RF_7_A2: C34_A2.2 L6_A2.1
RF_7_A3: C34_A3.2 L6_A3.1
RF_7_A4: C34_A4.2 L6_A4.1
RF_8_A1: C35_A1.2 L7_A1.1
RF_8_A2: C35_A2.2 L7_A2.1
RF_8_A3: C35_A3.2 L7_A3.1
RF_8_A4: C35_A4.2 L7_A4.1
RF_9_A1: C36_A1.2 L8_A1.1
RF_9_A2: C36_A2.2 L8_A2.1
RF_9_A3: C36_A3.2 L8_A3.1
RF_9_A4: C36_A4.2 L8_A4.1
RF_10_A1: R36_A1.1 R37_A1.2 R38_A1.1
RF_10_A2: R36_A2.1 R37_A2.2 R38_A2.1
RF_10_A3: R36_A3.1 R37_A3.2 R38_A3.1
RF_10_A4: R36_A4.1 R37_A4.2 R38_A4.1
RF_i_A1: R41_A1.2 R42_A1.1 U6_A1.8
RF_i_A2: R41_A2.2 R42_A2.1 U6_A2.8
RF_i_A3: R41_A3.2 R42_A3.1 U6_A3.8
RF_i_A4: R41_A4.2 R42_A4.1 U6_A4.8
RF_i_B1: R48_B1.2 R49_B1.1 U8_B1.8
RF_i_B2: R48_B2.2 R49_B2.1 U8_B2.8
RF_i_B3: R48_B3.2 R49_B3.1 U8_B3.8
RF_i_B4: R48_B4.2 R49_B4.1 U8_B4.8
RF_o_A1: C32_A1.2 R36_A1.2
RF_o_A2: C32_A2.2 R36_A2.2
RF_o_A3: C32_A3.2 R36_A3.2
RF_o_A4: C32_A4.2 R36_A4.2
RF_o_B1: C45_B1.2 R43_B1.2
RF_o_B2: C45_B2.2 R43_B2.2
RF_o_B3: C45_B3.2 R43_B3.2
RF_o_B4: C45_B4.2 R43_B4.2
RFi_A1: C32_A1.1 U5_A1.6
RFi_A2: C32_A2.1 U5_A2.6
RFi_A3: C32_A3.1 U5_A3.6
RFi_A4: C32_A4.1 U5_A4.6
RFi_B1: C45_B1.1 U7_B1.6
RFi_B2: C45_B2.1 U7_B2.6
RFi_B3: C45_B3.1 U7_B3.6
RFi_B4: C45_B4.1 U7_B4.6
RFo_A1: C31_A1.2 U5_A1.3
RFo_A2: C31_A2.2 U5_A2.3
RFo_A3: C31_A3.2 U5_A3.3
RFo_A4: C31_A4.2 U5_A4.3
RFo_B1: C44_B1.2 U7_B1.3
RFo_B2: C44_B2.2 U7_B2.3
RFo_B3: C44_B3.2 U7_B3.3
RFo_B4: C44_B4.2 U7_B4.3
RFout_A1: C31_A1.1 J7_A1.1
RFout_A2: C31_A2.1 J7_A2.1
RFout_A3: C31_A3.1 J7_A3.1
RFout_A4: C31_A4.1 J7_A4.1
SCLK: U1_M1.48 U4_LS2.11
SCLK_2: U1_M2.48 U4_LS1.11
SCLK_2_L: J2.5 J5.5 J6.A17 U4_LS1.2
SCLK_L: J2.6 J4.5 J6.B17 U4_LS2.2
SDIO_0: R3_M1.2 U1_M1.50 U4_LS3.9
SDIO_0_2: R3_M2.2 U1_M2.50 U4_LS4.9
SDIO_0_2_L: J2.19 J5.15 J6.A24 U4_LS4.4
SDIO_0_L: J2.20 J4.15 J6.B24 U4_LS3.4
SDIO_1: R4_M1.2 U1_M1.51 U4_LS3.10
SDIO_1_2: R4_M2.2 U1_M2.51 U4_LS4.10
SDIO_1_2_L: J2.17 J5.13 J6.A23 U4_LS4.3
SDIO_1_L: J2.18 J4.13 J6.B23 U4_LS3.3
SDIO_2: R5_M1.2 U1_M1.52 U4_LS3.11
SDIO_2_2: R5_M2.2 U1_M2.52 U4_LS4.11
SDIO_2_2_L: J2.15 J5.11 J6.A22 U4_LS4.2
SDIO_2_L: J2.16 J4.11 J6.B22 U4_LS3.2
SDIO_3: R6_M1.2 U1_M1.53 U4_LS3.12
SDIO_3_2: R6_M2.2 U1_M2.53 U4_LS4.12
SDIO_3_2_L: J2.13 J5.9 J6.A21 U4_LS4.1
SDIO_3_L: J2.14 J4.9 J6.B21 U4_LS3.1
SYNC_CLK: J2.24 J4.19 J6.B26 U1_M1.54
SYNC_CLK_2: J2.23 J5.19 J6.A26 U1_M2.54
SYNC_IN_2: R33.1 U1_M2.1
SYNC_IN_M1: TP4.1 U1_M1.1
SYNC_OUT: R33.2 U1_M1.2
SYNC_OUT_M2: TP5.1 U1_M2.2
VccA_LS1: C5_M1.2 C5_M2.2 C8_M1.2 C8_M2.2 C11_M1.2 C11_M2.2 C24.2 C29_LS1.2 C29_LS2.2 C29_LS3.2 C29_LS4.2 C39_A1.2 C39_A2.2 C39_A3.2 C39_A4.2 C40_A1.2 C40_A2.2 C40_A3.2 C40_A4.2 C52_B1.2 C52_B2.2 C52_B3.2 C52_B4.2 C53_B1.2 C53_B2.2 C53_B3.2 C53_B4.2 F2.2 FB1_M1.1 FB1_M2.1 FB5.2 R31.2 R34_LS1.2 R34_LS2.2 R34_LS3.2 R34_LS4.2 TP3.1 U1_M1.45 U1_M1.55 U1_M2.45 U1_M2.55 U4_LS1.14 U4_LS2.14 U4_LS3.14 U4_LS4.14 U6_A1.1 U6_A2.1 U6_A3.1 U6_A4.1 U8_B1.1 U8_B2.1 U8_B3.1 U8_B4.1
VccB_LS1: C4_M1.2 C4_M2.2 C7_M1.2 C7_M2.2 C10_M1.2 C10_M2.2 C18.2 C30_LS1.2 C30_LS2.2 C30_LS3.2 C30_LS4.2 C37_A1.2 C37_A2.2 C37_A3.2 C37_A4.2 C38_A1.2 C38_A2.2 C38_A3.2 C38_A4.2 C50_B1.2 C50_B2.2 C50_B3.2 C50_B4.2 C51_B1.2 C51_B2.2 C51_B3.2 C51_B4.2 F1.2 FB3.2 R7_M1.2 R7_M2.2 R28.2 TP2.1 U1_M1.49 U1_M2.49 U4_LS1.13 U4_LS2.13 U4_LS3.13 U4_LS4.13 U5_A1.1 U5_A2.1 U5_A3.1 U5_A4.1 U7_B1.1 U7_B2.1 U7_B3.1 U7_B4.1
pads on no net: FID1.1 FID2.1 FID3.1 FID4.1 FID5.1 FID6.1 J1.5 J1.6 J2.0 J2.1 J2.2 J2.4 J2.33 J2.34 J2.35 J2.36 J2.37 J2.38 J3.17 J3.19 J6.A12 J6.A27 J6.A28 J6.A29 J6.A30 J6.A31 J6.A32 J6.B12 J6.B27 J6.B28 J6.B29 J6.B30 J6.B31 J6.B32 T1_A1.5 T1_A2.5 T1_A3.5 T1_A4.5 T2_B1.5 T2_B2.5 T2_B3.5 T2_B4.5 U2.7 U3.7
copper on no net: | length 22.7
  TOP_L1 w0.25: 17.24,95.461 17.84,95.461 ; 17.84,91.441 v2(19.34,91.441) ; 17.84,92.361 17.84,93.441 ; 17.84,94.361 17.84,95.461 ; 18.42,95.461 17.84,95.461 ; 19.34,95.461 19.94,95.461 ; v2@19.44,91.441 v2(19.34,91.441) ; 19.94,92.361 19.94,93.441 ; 19.94,94.361 19.94,95.461 ; 20.52,95.461 19.94,95.461 ; 21.44,95.461 22.04,95.461 ; v2@21.54,91.441 v2(21.44,91.441) ; 22.04,92.361 22.04,93.441 ; 22.04,94.361 22.04,95.461 ; 22.64,95.461 22.04,95.461 ; 23.56,95.461 24.14,95.461 ; 24.14,91.441 v2(23.54,91.441) 22.04,91.441 v2(21.44,91.441) ; 24.14,92.361 24.14,93.441 ; 24.14,94.361 24.14,95.461 ; 24.74,95.461 24.14,95.461 ; v2(19.34,91.441) 19.94,91.441 v2(21.44,91.441)
  Bottom Layer_L8 w0.25: v2(18.44,91.461) 18.46,91.441 v2(19.34,91.441) ; v2(20.54,91.461) 20.56,91.441 v2(21.44,91.441) ; v2(22.64,91.461) 22.74,91.461 22.76,91.441 v2(23.54,91.441)

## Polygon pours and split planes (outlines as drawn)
GND on Plane_L2 (split plane): 245 vertices, not listed, extent 0.495,0.494 101.028,87.775
GND on Plane_L4 (split plane): 245 vertices, not listed, extent 0.495,0.494 101.028,87.775
GND on Plane_L5 (split plane): 245 vertices, not listed, extent 0.495,0.494 101.028,87.775
GND on Plane_L7 (split plane): 245 vertices, not listed, extent 0.495,0.494 101.028,87.775

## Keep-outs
Keep-Out Layer:
  lines w1.524: 0.762,86.932 0.762,4.509 15.737,4.509 ccw(c15.737,4.522) 15.75,4.522 15.75,10.868 ; 0.762,87.509 100.762,87.509 ; 15.687,19.599 cw(c16.568,19.599) 16.568,20.48 ; 34.074,11.749 34.074,3.512 ccw(c34.087,3.512) 34.087,3.499 42.087,3.499 ccw(c42.087,3.512) 42.1,3.512 42.1,9.959 ; 37.841,-38.601 55.283,-38.601 ; 79.264,1.209 79.264,11.694 100.762,11.694 100.762,86.932

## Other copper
Inner_L3:
  pour cut-out: 15.74,96.461 15.74,91.861 26.24,91.861 26.24,96.461
Bottom Layer_L8:
  rectangle: 15.24,90.261 26.84,96.461
Plane_L2 (plane layer: these items are gaps in the copper):
  pour cut-out: 15.74,96.461 15.74,91.861 26.24,91.861 26.24,96.461

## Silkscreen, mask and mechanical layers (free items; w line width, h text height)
Top Overlay:
  text "There is no copper under the filter" at 16.51,97.851 h0.7
  text "Only on the bottom side" at 18.034,96.842 h0.7
  text "chip1" at 81.28,80.111 h2
  text "chip2" at 74.422,79.73 h2
  text "RF SW" at 66.294,79.65 h2
Board Layer Stack Bottom Overlay:
  drawing of 14 lines, arcs and shapes, not listed
  text "+12V" at 85.725,81.217 h2.54 r270
  text "GND" at 92.71,81.09 h2.54 r270
  text "Quantum Source Labs LTD." at 94.234,38.926 h2.54
  text "Board P/N: ______________" at 94.107,36.513 h2.54
  text "S/N:____________________" at 94.107,34.1 h2.54
  text "Apr. 2023" at 94.247,31.085 h2.54
Board:
  lines w0.025: 0.762,88.285 ccw(c0.762,87.509) 0.043,87.221 ccw(c0.762,86.932) -0.013,86.932 -0.013,4.509 ccw(c0.762,4.509) 0.762,3.734 15.737,3.734 ccw(c15.737,4.522) 16.526,4.522 16.526,10.974 33.298,10.974 33.298,3.512 ccw(c34.087,3.512) 34.087,2.724 41.342,2.724 ccw(c41.342,3.512) 42.13,3.512 42.13,3.514 42.13,9.937 cw(c43.926,9.937) 42.292,10.683 42.309,10.69 cw(c43.926,9.959) 43.926,11.734 43.927,11.734 cw(c43.927,9.937) 45.723,9.937 45.723,0.517 45.737,0.492 46.244,-0.009 46.262,-0.017 56.491,-0.017 56.509,-0.009 57.013,0.495 57.021,0.513 57.021,8.183 cw(c57.815,8.183) 57.815,8.978 58.009,8.978 cw(c58.009,8.187) 58.8,8.187 58.8,0.522 58.826,0.496 78.96,0.496 ccw(c79.264,1.209) 79.569,0.496 80.026,0.496 80.053,0.522 80.053,10.919 100.762,10.919 ccw(c100.762,11.694) 101.538,11.694 101.538,86.932 ; 0.762,88.285 100.762,88.285 cw(c100.762,87.509) 101.538,87.509 ; 0.762,88.285 0.762,88.285 ; 101.538,86.933 ccw(c100.762,86.932) 101.482,87.221 ccw(c100.762,87.509) 101.538,87.509 ; 101.538,86.933 101.538,86.932 ; 101.538,87.509 101.538,87.509
FAB_DWG_INFO:
  circle w0.025: c70.756,-24.791 r0.217
  circle w0.025: c70.121,-22.632 r0.217
  pour cut-out: 74.382,-24.671 74.084,-25.449 76.567,-25.955 74.382,-24.671
  pour cut-out: 63.489,-23.314 63.514,-22.482 61.003,-22.82 63.489,-23.314
  pour cut-out: 63.503,-30.165 63.503,-30.999 61.003,-30.582 63.503,-30.165
  pour cut-out: 56.733,-30.165 56.733,-30.999 59.233,-30.582 56.733,-30.165
  pour cut-out: 46.263,-60.523 47.096,-60.523 46.68,-63.023 46.263,-60.523
  pour cut-out: 46.263,-67.333 47.096,-67.333 46.68,-64.833 46.263,-67.333
  lines w0.025: 26.006,-30.582 56.733,-30.582 ; 30.705,-69.807 46.68,-69.807 ; 45.43,-64.833 59.368,-64.833 ; 45.43,-63.023 58.608,-63.023 ; 46.68,-69.833 46.68,-67.333 ; 46.68,-64.833 46.68,-63.023 ; 46.68,-60.523 46.68,-58.023 ; 59.233,-31.832 59.233,-27.064 ; 59.233,-30.582 61.003,-30.582 ; 59.233,-26.439 59.233,-63.023 59.993,-64.833 60.243,-64.833 61.003,-63.023 61.003,-26.439 ; 60.118,-64.567 60.118,-60.823 ; 60.118,-60.529 60.118,-58.065 ; 60.118,-57.76 60.118,-56.566 ; 60.118,-56.312 60.118,-52.568 ; 60.118,-52.274 60.118,-49.81 ; 60.118,-49.505 60.118,-48.311 ; 60.118,-48.057 60.118,-44.313 ; 60.118,-44.019 60.118,-41.555 ; 60.118,-41.25 60.118,-40.056 ; 60.118,-39.802 60.118,-36.058 ; 60.118,-35.764 60.118,-33.3 ; 60.118,-32.995 60.118,-31.801 ; 60.118,-31.547 60.118,-27.803 ; 60.118,-27.509 60.118,-25.045 ; 60.118,-24.74 60.118,-23.546 ; 60.118,-23.292 60.118,-19.548 ; 61.003,-31.832 61.003,-27.064 ; 61.003,-25.814 61.003,-21.57 ; 61.318,-62.273 63.932,-56.047 64.174,-55.47 77.051,-24.803 ; 63.502,-22.898 cw(c61.003,-63.023) 64.691,-22.99 ; 63.503,-30.582 66.003,-30.582 ; 73.191,-24.712 cw(c61.003,-63.023) 74.233,-25.06
  lines w0.127: 40.613,-80.119 77.697,-80.119 ; 40.613,-79.865 77.697,-79.865
  text "There is no copper under the filter" at 11.704,103.905 h1
  text "Only on the bottom side" at 14.904,101.805 h1
  text "There is no copper under the filter" at 19.109,101.097 h1
  text "There is no copper under the filter" at 8.91,100.402 h1
  text "Only on the bottom side" at 12.11,98.302 h1
  text "General Notes for PCB production:" at 118.007,85.835 h5
  text "1. General:" at 117.065,80.829 h3
  text "1.1 Drill per drilling table on the drill drawing." at 121.114,78.341 h3
  text "1.2 All holes sizes are after platind." at 121.114,75.841 h3
  text "1.3 Manufacturing per IPC-6012-A (last version)." at 121.114,73.341 h3
  text "1.4 General tolerance: +/-0.2mm unless otherwise specified/" at 121.114,70.841 h3
  text "1.5 Hole size tolerance: +/-0.1mm +/-0.05mm, unless otherwise specified/" at 121.114,68.341 h3
  text "1.6 Each production batch/lot should be delivered with a C.O.C. and test report." at 121.114,65.841 h3
  text "2. Material:" at 117.114,63.341 h3
  text "2.1 Class epoxy FR4 Total thickness: 1.6 mm +/-10%" at 121.114,60.841 h3
  text "2.2 Material should be fire resistance and UL-94V-0 recognized." at 121.114,58.341 h3
  text "2.3.NO. OF LAYERS: 8LAYERS." at 121.114,55.841 h3
  text "3. Plating:" at 117.114,53.341 h3
  text "3.1 ROHS complieant immersion gold (gold 0.05um min.+nickel 3um min.) ,HI TG-170." at 121.114,50.841 h3
  text "3.2 All holes to be plated thru, except noted else." at 121.114,48.341 h3
  text "4. Solder mask:" at 117.114,45.841 h3
  text "4.1 Solder mask per IPC-SM-840M." at 121.114,43.341 h3
  text "4.2 Solder mask type:wet photoimageable class 2, color green on both sides of the board." at 121.114,40.841 h3
  text "4.3 Solder mask over copper to cover all traces completety." at 121.114,38.341 h3
  text "5. Marking:" at 117.241,35.5 h3
  text "5.1 All the markings on the board should be with proxy ink, both sides unless otherwise." at 121.241,33 h3
  text "5.2 Board to be marked with manufacturing code which mets U.L.  flammability rating 94V-0, or better." at 121.241,30.5 h3
  text "5.3 E.S.D. symbol to be marked with yellow / white epoxy ink." at 121.241,28 h3
  text "6. Final test:" at 117.241,25.5 h3
  text "6.1 Each board to be visual and mechanical tested per IPC-A-600 class 2 workmanship standart." at 121.241,23 h3
  text "6.2 Bow and twist per IPC-TM-650 wrap age shall not exceed 0.75%," at 121.241,20.5 h3
  text "each board must be measured on each corner." at 126.741,18 h3
  text "DETAIL A" at 93.999,3.602 h3.17
  text "20" at 67.784,-24.105 h1.27
  text "+/- 5" at 66.867,-25.8 h0.79
  text "1.57" at 26.382,-29.515 h1.27
  text "MAX OVER PLATING" at 32.683,-29.597 h1.27
  text "0.062" at 28.503,-34.176 h1.27
  text "[" at 26.666,-34.812 h3.17
  text "]" at 33.847,-34.856 h3.17
  text "+0,25" at 23.306,-64.154 h0.79
  text "1,3" at 17.01,-65.482 h1.27
  text "-0,25" at 23.306,-66.404 h0.79
  text "+,010" at 23.412,-69.654 h0.79
  text "0,051" at 15.968,-70.993 h1.27
  text "-,010" at 23.412,-71.904 h0.79
  text "[" at 13.636,-71.983 h3.17
  text "]" at 27.786,-71.983 h3.17
  text "DETAIL A" at 40.486,-78.849 h3.17
FAB:
  lines w0.254: 205.214,12.037 205.214,111.072

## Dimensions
0.737,6.509 to 100.762,88.285 on FAB_DWG_INFO
0.737,8.509 to 101.538,86.933 on FAB_DWG_INFO
0.737,7.509 to 101.538,86.932 on FAB_DWG_INFO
